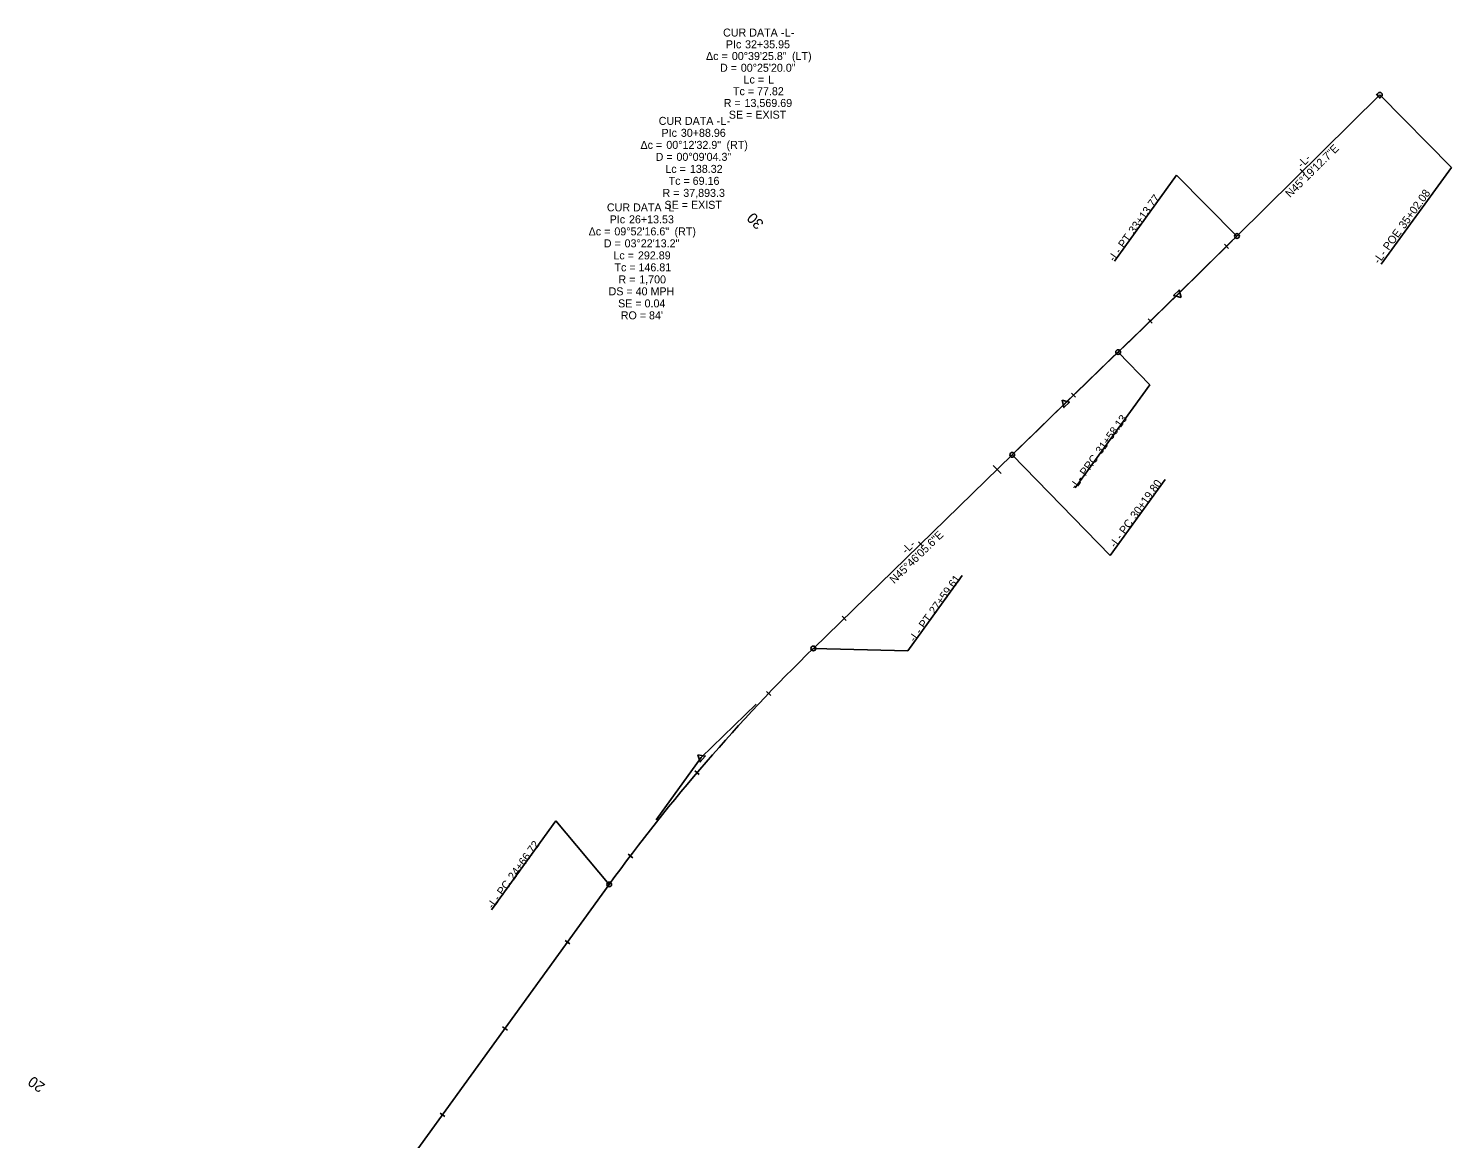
# Model space of a CAD drawing. Extents: x 1183553 to 1185476, y 573018 to 575071.
# Drawn here: x 1184142 to 1185476, y 574030 to 575071 of the extents above; entities that cross this region are included whole.
import ezdxf

# ---------------------------------------------------------------- set-up
doc = ezdxf.new("R2010")
doc.units = 0
for name, color, linetype in [('CTL Secondary Horizontal and Vertical Cogo Number', 7, 'Continuous'), ('Default', 7, 'Continuous'), ('Exist Utilities Telephone Hand Hole CELL', 7, 'Continuous'), ('Exist Utilities Telephone Hand Hole Cogo Elevation', 7, 'Continuous'), ('Exist Utilities Telephone Hand Hole Cogo Number', 7, 'Continuous'), ('Exist Utilities Telephone UG Conduit SUE LOS B Cogo Comment', 7, 'Continuous'), ('Exist Utilities Telephone UG Conduit SUE LOS B Cogo Elevation', 7, 'Continuous'), ('Exist Utilities Telephone UG Conduit SUE LOS B Cogo Number', 7, 'Continuous')]:
    doc.layers.add(name, color=color, linetype=linetype)

msp = doc.modelspace()

# ---------------------------------------------------------------- linework, layer by layer
at = {"layer": 'CTL Secondary Horizontal and Vertical Cogo Number'}
for p, q in [((1185274.5, 574875.9), (1185408.4, 575008.3)), ((1184877.5, 574489.3), (1185063.9, 574670.8)), ((1184334.3, 573781.9), (1184686.2, 574268))]:
    msp.add_line(p, q, dxfattribs=at)
for centre, radius, start, end in [((1175733, 584524.6), 13569.7, 314.02263, 314.67981), ((1211496.9, 547519.4), 37893.3, 134.02263, 134.23178), ((1186063.3, 573271.2), 1700, 134.2318, 144.103)]:
    msp.add_arc(centre, radius, start, end, dxfattribs=at)
at = {"layer": 'Default'}
for p, q in [((1185274.5, 574875.9), (1185408.4, 575008.3)), ((1185219.2, 574821.2), (1185270.3, 574871.8)), ((1185219.2, 574821.2), (1185167.4, 574771.2)), ((1185219.2, 574821.2), (1185219.2, 574821.2)), ((1185113.5, 574719.1), (1185165.2, 574769.1)), ((1185113.5, 574719.1), (1185061.9, 574668.8)), ((1185113.5, 574719.1), (1185113.5, 574719.1)), ((1184877.5, 574489.3), (1185063.9, 574670.8)), ((1184772.3, 574386.9), (1184823.9, 574437.1)), ((1184772.3, 574386.9), (1184730.1, 574328.6)), ((1184772.3, 574386.9), (1184772.3, 574386.9)), ((1184334.3, 573781.9), (1184686.2, 574268))]:
    msp.add_line(p, q, dxfattribs=at)
for points in [[(1185222.1, 574818.2), (1185220.3, 574825.2), (1185215.1, 574820.2)], [(1185110.6, 574722), (1185112.3, 574715.1), (1185117.5, 574720.1)], [(1184769.1, 574389.6), (1184771.5, 574382.8), (1184776.2, 574388.3)]]:
    msp.add_lwpolyline(points, close=True, dxfattribs=at)
for centre, radius, start, end in [((1175733, 584524.6), 13569.7, 314.02263, 314.67981), ((1211496.9, 547519.4), 37893.3, 134.02263, 134.23178), ((1186063.3, 573271.2), 1700, 134.2318, 144.103)]:
    msp.add_arc(centre, radius, start, end, dxfattribs=at)
at = {"layer": 'Exist Utilities Telephone Hand Hole CELL'}
for p, q in [((1185408.4, 575008.3), (1185475.6, 574940.3)), ((1185475.6, 574940.3), (1185409.8, 574849.4)), ((1185218, 574933), (1185159.7, 574852.4)), ((1185274.5, 574875.9), (1185218, 574933)), ((1185163.2, 574767.1), (1185192.9, 574736.4)), ((1185192.9, 574736.4), (1185122.9, 574639.7)), ((1185063.9, 574670.8), (1185155.7, 574576.5)), ((1185155.7, 574576.5), (1185207.2, 574647.6)), ((1184966, 574487), (1185017, 574557.5)), ((1184877.5, 574489.3), (1184966, 574487)), ((1184636.3, 574327.6), (1184575.7, 574244.1)), ((1184686.2, 574268), (1184636.3, 574327.6))]:
    msp.add_line(p, q, dxfattribs=at)
for centre in [(1185408.4, 575008.3), (1185274.5, 574875.9), (1185163.2, 574767.1), (1185063.9, 574670.8), (1184877.5, 574489.3), (1184686.2, 574268)]:
    msp.add_circle(centre, 2.25, dxfattribs=at)
at = {"layer": 'Exist Utilities Telephone UG Conduit SUE LOS B Cogo Elevation'}
msp.add_line((1185046, 574660.8), (1185053.4, 574653.2), dxfattribs=at)
at = {"layer": 'Exist Utilities Telephone UG Conduit SUE LOS B Cogo Number'}
for p, q in [((1185405, 575008.8), (1185408.8, 575004.9)), ((1185333.9, 574938.5), (1185337.7, 574934.6)), ((1185262.8, 574868.2), (1185266.6, 574864.3)), ((1185191.3, 574798.3), (1185195.2, 574794.3)), ((1185119.5, 574728.7), (1185123.3, 574724.7)), ((1184976.1, 574589.2), (1184980, 574585.3)), ((1184904.5, 574519.5), (1184908.3, 574515.5)), ((1184833.5, 574448.9), (1184837.5, 574445.1)), ((1184766.4, 574374.6), (1184770.6, 574371)), ((1184703.8, 574296.4), (1184708.2, 574293.1)), ((1184644.8, 574215.6), (1184649.3, 574212.3)), ((1184586.2, 574134.5), (1184590.7, 574131.3)), ((1184527.6, 574053.5), (1184532, 574050.3))]:
    msp.add_line(p, q, dxfattribs=at)

# ---------------------------------------------------------------- texts
at = {"layer": 'Exist Utilities Telephone Hand Hole CELL'}
for s, p in [('33+13.77', (1185178.2, 574877.2)), ('35+02.08', (1185431.5, 574882.1)), ('POE', (1185416.8, 574861.9)), ('PT', (1185168.6, 574864)), ('L', (1185161.4, 574854.1)), ('-', (1185159.4, 574851.3)), ('- ', (1185164.9, 574858.8)), ('L', (1185409.7, 574852)), ('- ', (1185413.1, 574856.7)), ('-', (1185407.6, 574849.1)), ('31+58.13', (1185147.3, 574670.7)), ('PRC', (1185132.6, 574650.4)), ('L', (1185125.4, 574640.5)), ('-', (1185123.4, 574637.7)), ('- ', (1185128.8, 574645.2)), ('30+19.80', (1185179.9, 574610)), ('PC', (1185169.6, 574595.8)), ('L', (1185162.5, 574585.9)), ('- ', (1185165.9, 574590.6)), ('-', (1185160.4, 574583.1)), ('27+59.61', (1184991.3, 574520.6)), ('PT', (1184981.7, 574507.4)), ('L', (1184974.5, 574497.5)), ('-', (1184972.5, 574494.7)), ('- ', (1184978, 574502.2)), ('24+66.72', (1184596.7, 574271.4)), ('PC', (1184586.4, 574257.2)), ('- ', (1184582.7, 574252.1)), ('L', (1184579.3, 574247.3)), ('-', (1184577.2, 574244.5))]:
    msp.add_text(s, height=7.5, rotation=54.103, dxfattribs=at).set_placement(p)
at = {"layer": 'Exist Utilities Telephone Hand Hole Cogo Elevation'}
for s, p in [('CUR DATA -', (1184792.9, 575062.9)), ('L', (1184850.7, 575062.9)), ('PIc ', (1184795.5, 575051.9)), ('32+35.95', (1184813.5, 575051.9)), ('-', (1184856.5, 575062.9)), ('Δc = ', (1184776.9, 575040.9)), ('00°39\'25.8"', (1184801.1, 575040.9)), (' (LT)', (1184854.7, 575040.9)), ('D = ', (1184790, 575029.9)), ('00°25\'20.0"', (1184809.5, 575029.9)), ('Tc = ', (1184802.2, 575007.9)), ('Lc = ', (1184812.1, 575018.9)), ('77.82', (1184824.7, 575007.9)), ('L', (1184835.1, 575018.9)), ('R = ', (1184793.5, 574996.9)), ('13,569.69', (1184813, 574996.9)), ('SE = EXIST', (1184798.3, 574985.9)), ('CUR DATA -', (1184732.6, 574980.1)), ('PIc ', (1184735.2, 574968.9)), ('30+88.96', (1184753.3, 574968.9)), ('L', (1184790.4, 574980.1)), ('-', (1184796.3, 574980.1)), ('Δc = ', (1184715.5, 574957.6)), ('00°12\'32.9"', (1184739.7, 574957.6)), (' (RT)', (1184793.3, 574957.6)), ('D = ', (1184729.7, 574946.4)), ('00°09\'04.3"', (1184749.2, 574946.4)), ('Lc = ', (1184738.8, 574935.1)), ('138.32', (1184761.8, 574935.1)), ('Tc = ', (1184741.9, 574923.9)), ('69.16', (1184764.4, 574923.9)), ('R = ', (1184736.1, 574912.6)), ('SE = EXIST', (1184738, 574901.4)), ('37,893.3', (1184755.6, 574912.6)), ('CUR DATA -', (1184684, 574899)), ('PIc ', (1184686.6, 574887.8)), ('26+13.53', (1184704.7, 574887.8)), ('L', (1184741.8, 574899)), ('-', (1184747.6, 574899)), ('Δc = ', (1184666.9, 574876.5)), ('09°52\'16.6"', (1184691, 574876.5)), (' (RT)', (1184744.6, 574876.5)), ('D = ', (1184681.1, 574865.3)), ('03°22\'13.2"', (1184700.6, 574865.3)), ('Lc = ', (1184690.1, 574854)), ('292.89', (1184713.1, 574854)), ('Tc = ', (1184691.1, 574842.8)), ('146.81', (1184713.6, 574842.8)), ('DS = 40 MPH', (1184685.6, 574820.3)), ('R = ', (1184694.8, 574831.5)), ('1,700', (1184714.3, 574831.5)), ('SE = 0.04', (1184694.5, 574809)), ("RO = 84'", (1184697, 574797.8))]:
    msp.add_text(s, height=7.5, dxfattribs=at).set_placement(p)
at = {"layer": 'Exist Utilities Telephone Hand Hole Cogo Number'}
for s, rotation, p in [('N45°19\'12.7"E', 44.6798, (1185324.3, 574911.4)), ('L', 44.6798, (1185337.9, 574941.8)), ('-', 44.6798, (1185342, 574945.9)), ('-', 44.6798, (1185335.4, 574939.3)), ('N45°46\'05.6"E', 44.2318, (1184953.3, 574549.5)), ('-', 44.2318, (1184971.3, 574583.8)), ('L', 44.2318, (1184967.1, 574579.8)), ('-', 44.2318, (1184964.6, 574577.3))]:
    msp.add_text(s, height=7.5, rotation=rotation, dxfattribs=at).set_placement(p)
at = {"layer": 'Exist Utilities Telephone UG Conduit SUE LOS B Cogo Comment'}
for s, rotation, p in [('30', 134.2318, (1184831.8, 574888.1)), ('20', 144.103, (1184158.2, 574080.2))]:
    msp.add_text(s, height=10, rotation=rotation, dxfattribs=at).set_placement(p)

doc.saveas('drawing.dxf')
